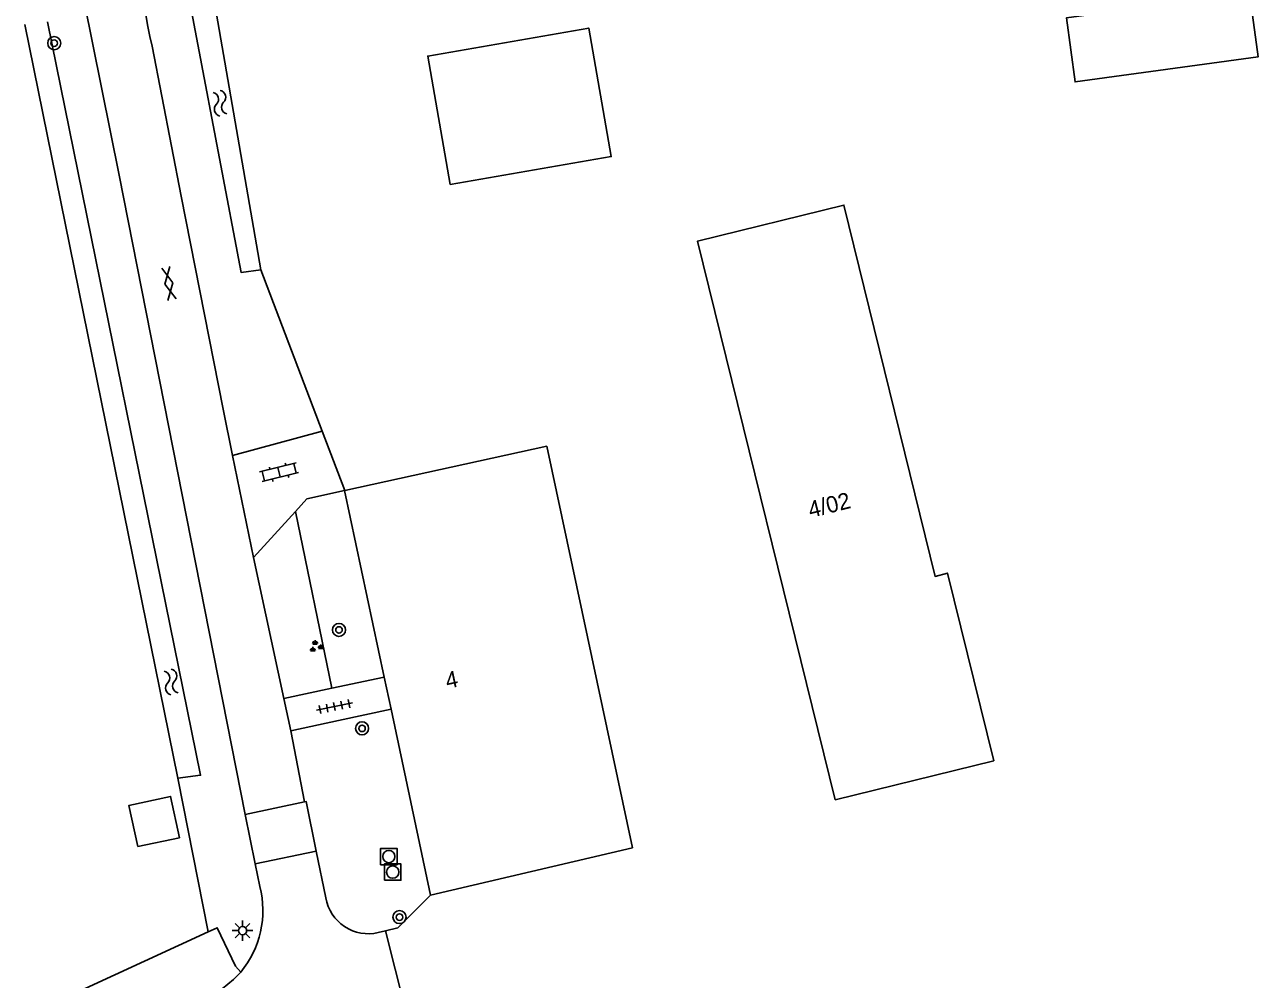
# Model space of a CAD drawing. Extents: x 134297 to 137000, y 403500 to 406000.
# Drawn here: x 136337.1 to 136412.3, y 405336.3 to 405394.6 of the extents above; entities that cross this region are included whole.
import ezdxf

# ---------------------------------------------------------------- set-up
doc = ezdxf.new("R2010")
doc.units = 0
for name, color, linetype in [('gg-anno-huisnummerreeks BGT', 7, 'Continuous'), ('gg-bbg-bijgebouw', 7, 'Continuous'), ('gg-bbg-gedigitaliseerde bijgebouw', 7, 'Continuous'), ('gg-bbg-hoofdgebouw', 7, 'Continuous'), ('gg-knt-verharding', 7, 'Continuous'), ('gg-kntw-bovenkant insteek waterloop', 7, 'Continuous'), ('gt-grn-groengrens', 7, 'Continuous'), ('gt-grn-vlakafsluiter', 7, 'Continuous'), ('gt-grn-weggrens', 7, 'Continuous'), ('gt-symb-boom', 7, 'Continuous'), ('gt-symb-gesloten verharding', 7, 'Continuous'), ('gt-symb-groenvak', 7, 'Continuous'), ('gt-symb-klinker verharding', 7, 'Continuous'), ('gt-symb-lichtmast', 7, 'Continuous'), ('gt-symb-rioolschacht', 7, 'Continuous'), ('gt-symb-tegel verharding', 7, 'Continuous'), ('gt-symb-watersymbool', 7, 'Continuous')]:
    doc.layers.add(name, color=color, linetype=linetype)

# ---------------------------------------------------------------- blocks, each defined once
blk = doc.blocks.new('gt0-BOOM')
at = {"layer": 'gt-symb-boom'}
for radius in [0.4, 0.2]:
    blk.add_circle((0, 0), radius, dxfattribs=at)
blk = doc.blocks.new('gt0-RS')
at = {"layer": 'gt-symb-rioolschacht'}
blk.add_lwpolyline([(-0.5, -0.5), (0.5, -0.5), (0.5, 0.5), (-0.5, 0.5)], close=True, dxfattribs=at)
blk.add_circle((0, 0), 0.375, dxfattribs=at)
blk = doc.blocks.new('gt0-KL1')
at = {"layer": 'gt-symb-klinker verharding'}
for p, q in [((-1.15, 0.3), (1.15, 0.3)), ((-1, -0.3), (-1, 0.3)), ((-0.5, 0.3), (-0.5, 0.45)), ((0, -0.3), (0, 0.3)), ((0.5, 0.3), (0.5, 0.45)), ((1, -0.3), (1, 0.3)), ((-1.15, -0.3), (1.15, -0.3)), ((-0.5, -0.45), (-0.5, -0.3)), ((0.5, -0.45), (0.5, -0.3))]:
    blk.add_line(p, q, dxfattribs=at)
blk = doc.blocks.new('gt0-GRVAK')
at = {"layer": 'gt-symb-groenvak'}
for p, q in [((-0.11, 0.189), (-0.228, 0.24)), ((-0.182, 0.153), (0.088, 0.153)), ((-0.091, 0.211), (-0.156, 0.322)), ((-0.047, 0.214), (-0.047, 0.393)), ((-0.004, 0.211), (0.061, 0.322)), ((0.015, 0.189), (0.133, 0.24)), ((0.262, -0.052), (0.197, 0.059)), ((0.305, -0.049), (0.305, 0.13)), ((0.349, -0.052), (0.414, 0.059)), ((-0.245, -0.228), (-0.363, -0.177)), ((-0.318, -0.264), (-0.047, -0.264)), ((-0.226, -0.206), (-0.291, -0.095)), ((-0.183, -0.203), (-0.183, -0.024)), ((-0.139, -0.206), (-0.074, -0.095)), ((-0.12, -0.228), (-0.002, -0.177)), ((0.243, -0.074), (0.125, -0.023)), ((0.17, -0.11), (0.441, -0.11)), ((0.368, -0.074), (0.486, -0.023))]:
    blk.add_line(p, q, dxfattribs=at)
blk = doc.blocks.new('gt0-TEG1')
at = {"layer": 'gt-symb-tegel verharding'}
for p, q in [((-1.125, 0), (1.125, 0)), ((-0.9, -0.25), (-0.9, 0.25)), ((-0.45, -0.25), (-0.45, 0.25)), ((0, -0.25), (0, 0.25)), ((0.45, -0.25), (0.45, 0.25)), ((0.9, -0.25), (0.9, 0.25))]:
    blk.add_line(p, q, dxfattribs=at)
blk = doc.blocks.new('gt0-LMAST')
at = {"layer": 'gt-symb-lichtmast'}
for p, q in [((-0.182, 0.173), (-0.447, 0.438)), ((-0.005, 0.246), (-0.005, 0.621)), ((0.172, 0.173), (0.437, 0.438)), ((-0.255, -0.004), (-0.63, -0.004)), ((-0.182, -0.181), (-0.447, -0.446)), ((-0.005, -0.254), (-0.005, -0.629)), ((0.437, -0.446), (0.172, -0.181)), ((0.245, -0.004), (0.62, -0.004))]:
    blk.add_line(p, q, dxfattribs=at)
blk.add_circle((-0.005, -0.004), 0.25, dxfattribs=at)
blk = doc.blocks.new('gt0-GESVH1')
at = {"layer": 'gt-symb-gesloten verharding'}
for p, q in [((-0.992, -0.261), (0.008, 0.239)), ((0.008, -0.261), (-0.992, 0.239)), ((0.008, 0.239), (1.008, -0.261)), ((1.008, 0.239), (0.008, -0.261))]:
    blk.add_line(p, q, dxfattribs=at)
blk = doc.blocks.new('gt0-WA')
at = {"layer": 'gt-symb-watersymbool'}
for centre, start, end in [((-0.323, 0.022), 28.07249, 151.92751), ((0.427, 0.422), 208.07248, 331.92751), ((-0.323, -0.428), 28.07249, 151.92751), ((0.427, -0.028), 208.07248, 331.92751)]:
    blk.add_arc(centre, 0.425, start, end, dxfattribs=at)

msp = doc.modelspace()

# ---------------------------------------------------------------- linework, layer by layer
at = {"layer": 'gg-bbg-bijgebouw'}
for points in [[(136363.018, 405384.804), (136361.649, 405392.646), (136371.472, 405394.361), (136372.841, 405386.519), (136363.018, 405384.804)], [(136343.961, 405344.392), (136343.421, 405346.912), (136345.961, 405347.461), (136346.501, 405344.932), (136343.961, 405344.392)]]:
    msp.add_lwpolyline(points, dxfattribs=at)
at = {"layer": 'gg-bbg-gedigitaliseerde bijgebouw'}
msp.add_lwpolyline([(136411.779, 405396.516), (136400.604, 405394.983), (136401.14, 405391.074), (136412.315, 405392.607), (136411.779, 405396.516)], dxfattribs=at)
at = {"layer": 'gg-bbg-hoofdgebouw'}
for p, q in [((136356.589, 405366.125), (136368.903, 405368.829)), ((136374.144, 405344.312), (136368.903, 405368.829)), ((136356.579, 405366.123), (136356.589, 405366.125)), ((136356.579, 405366.123), (136358.995, 405354.744)), ((136358.995, 405354.744), (136359.413, 405352.774)), ((136359.413, 405352.774), (136361.821, 405341.431)), ((136361.821, 405341.431), (136374.144, 405344.312))]:
    msp.add_line(p, q, dxfattribs=at)
msp.add_lwpolyline([(136396.171, 405349.622), (136386.511, 405347.251), (136378.111, 405381.362), (136387.031, 405383.552), (136392.601, 405360.891), (136393.351, 405361.091), (136396.171, 405349.622)], dxfattribs=at)
at = {"layer": 'gg-knt-verharding'}
for p, q in [((136342.823, 405385.383), (136340.686, 405395.991)), ((136342.823, 405385.383), (136350.503, 405346.363)), ((136349.746, 405368.275), (136355.213, 405369.749)), ((136349.746, 405368.275), (136351.012, 405362.044)), ((136354.274, 405365.628), (136356.579, 405366.123)), ((136353.573, 405364.857), (136354.274, 405365.628)), ((136351.012, 405362.044), (136353.573, 405364.857)), ((136351.012, 405362.044), (136352.872, 405353.433)), ((136355.804, 405354.061), (136358.995, 405354.744)), ((136352.872, 405353.433), (136355.804, 405354.061)), ((136352.872, 405353.433), (136353.299, 405351.453)), ((136359.413, 405352.774), (136356.213, 405352.083)), ((136356.213, 405352.083), (136353.299, 405351.453)), ((136354.125, 405347.12), (136353.299, 405351.453)), ((136354.125, 405347.12), (136350.503, 405346.363)), ((136350.503, 405346.363), (136351.126, 405343.345)), ((136354.847, 405344.107), (136351.126, 405343.345)), ((136355.439, 405341.261), (136354.847, 405344.107)), ((136351.126, 405343.345), (136351.405, 405341.951)), ((136361.821, 405341.431), (136359.822, 405339.426)), ((136359.822, 405339.426), (136359.08, 405339.26)), ((136348.249, 405339.183), (136338.672, 405334.775)), ((136359.08, 405339.26), (136358.626, 405339.146)), ((136361.976, 405327.594), (136359.08, 405339.26))]:
    msp.add_line(p, q, dxfattribs=at)
for points in [[(136344.829, 405393.258), (136346.608, 405384.105), (136349.173, 405371.095), (136349.746, 405368.275)], [(136354.847, 405344.107), (136354.239, 405347.138), (136354.125, 405347.12)], [(136350.241, 405336.732), (136349.921, 405337.094), (136348.804, 405339.439), (136348.249, 405339.183)], [(136350.241, 405336.732), (136349.792, 405336.278), (136347.375, 405334.289)]]:
    msp.add_lwpolyline(points, dxfattribs=at)
for centre, radius, start, end in [((136393.46, 405403.922), 49.787, 169.97933, 192.36826), ((136345.708, 405340.482), 5.884, 320.39985, 14.45421), ((136358.018, 405341.689), 2.614, 189.41286, 283.44797)]:
    msp.add_arc(centre, radius, start, end, dxfattribs=at)
at = {"layer": 'gg-kntw-bovenkant insteek waterloop'}
for p, q in [((136348.061, 405399.322), (136351.47, 405379.604)), ((136337.059, 405394.569), (136346.403, 405348.573))]:
    msp.add_line(p, q, dxfattribs=at)
for points in [[(136351.47, 405379.604), (136350.273, 405379.436), (136346.295, 405400.337)], [(136346.403, 405348.573), (136347.786, 405348.745), (136338.442, 405394.741)]]:
    msp.add_lwpolyline(points, dxfattribs=at)
at = {"layer": 'gt-grn-groengrens'}
for p, q in [((136351.47, 405379.604), (136355.213, 405369.749)), ((136353.573, 405364.857), (136355.804, 405354.061))]:
    msp.add_line(p, q, dxfattribs=at)
at = {"layer": 'gt-grn-vlakafsluiter'}
msp.add_line((136346.403, 405348.573), (136348.249, 405339.183), dxfattribs=at)
at = {"layer": 'gt-grn-weggrens'}
msp.add_line((136355.213, 405369.749), (136356.589, 405366.125), dxfattribs=at)

# ---------------------------------------------------------------- block references
at = {"layer": 'gt-symb-boom'}
for p in [(136338.863, 405393.439), (136356.233, 405357.62), (136357.64, 405351.612), (136359.927, 405340.092)]:
    msp.add_blockref('gt0-BOOM', p, dxfattribs=at)
at = {"layer": 'gt-symb-gesloten verharding', "rotation": -79.28535610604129}
msp.add_blockref('gt0-GESVH1', (136345.869, 405378.778), dxfattribs=at)
at = {"layer": 'gt-symb-groenvak'}
msp.add_blockref('gt0-GRVAK', (136354.82, 405356.605), dxfattribs=at)
at = {"layer": 'gt-symb-klinker verharding', "rotation": 13.93901435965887}
msp.add_blockref('gt0-KL1', (136352.581, 405367.248), dxfattribs=at)
at = {"layer": 'gt-symb-lichtmast'}
msp.add_blockref('gt0-LMAST', (136350.356, 405339.27), dxfattribs=at)
at = {"layer": 'gt-symb-rioolschacht'}
for p in [(136359.274, 405343.784), (136359.508, 405342.842)]:
    msp.add_blockref('gt0-RS', p, dxfattribs=at)
at = {"layer": 'gt-symb-tegel verharding', "rotation": 11.366137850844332}
msp.add_blockref('gt0-TEG1', (136355.954, 405352.942), dxfattribs=at)
at = {"layer": 'gt-symb-watersymbool'}
for p, rotation in [((136348.987, 405389.725), 106.0241096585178), ((136346.005, 405354.392), 106.02410965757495)]:
    msp.add_blockref('gt0-WA', p, dxfattribs=dict(at, rotation=rotation))

# ---------------------------------------------------------------- texts
at = {"layer": 'gg-anno-huisnummerreeks BGT'}
for s, rotation, p in [('4/02', 13.8, (136384.995, 405364.454)), ('4', 12, (136362.841, 405354.019))]:
    msp.add_text(s, height=1, rotation=rotation, dxfattribs=at).set_placement(p)

doc.saveas('drawing.dxf')
